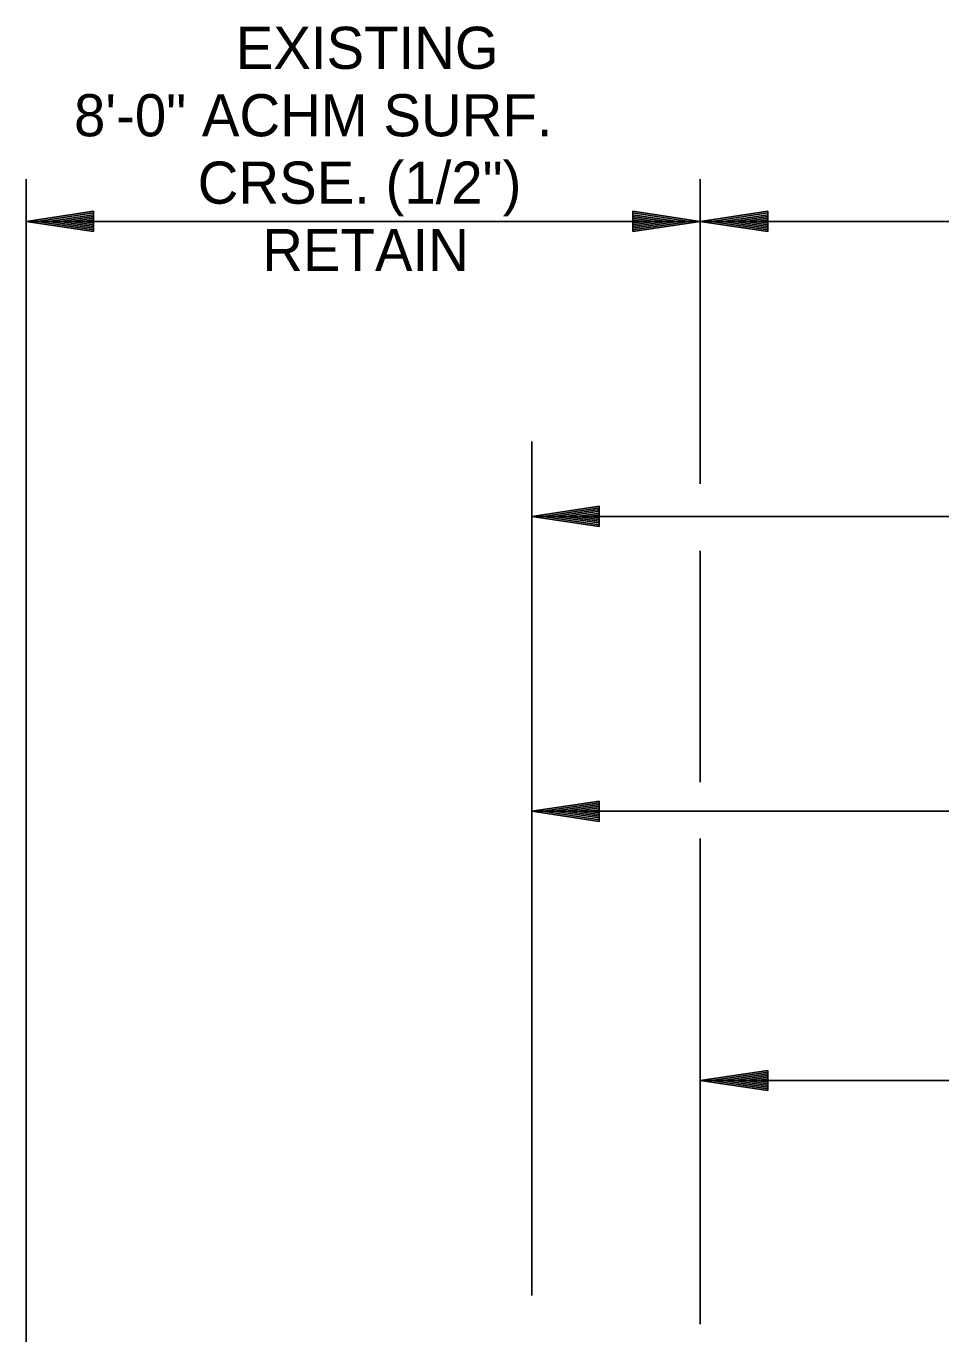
# Model space of a CAD drawing. Extents: x 60325 to 61047, y 53669 to 53767.
# Drawn here: x 60526.55 to 60537.4, y 53740.39 to 53755.91 of the extents above; entities that cross this region are included whole.
import ezdxf

# ---------------------------------------------------------------- set-up
doc = ezdxf.new("R2010")
doc.units = 0
doc.layers.add('R_Border', color=7, linetype='Continuous')
doc.layers.add('R_Border Prem', color=7, linetype='Continuous')

msp = doc.modelspace()

# ---------------------------------------------------------------- linework, layer by layer
at = {"layer": 'R_Border'}
for p, q in [((60534.545, 53740.505), (60534.545, 53744.102)), ((60535.345, 53743.516), (60534.545, 53743.396)), ((60535.345, 53743.496), (60534.679, 53743.396)), ((60535.345, 53743.516), (60535.345, 53743.276)), ((60535.345, 53743.276), (60534.545, 53743.396)), ((60534.545, 53743.396), (60562.545, 53743.396)), ((60535.345, 53743.296), (60534.679, 53743.396)), ((60535.345, 53743.476), (60534.816, 53743.396)), ((60535.345, 53743.317), (60534.816, 53743.396)), ((60535.345, 53743.456), (60534.95, 53743.396)), ((60535.345, 53743.337), (60534.95, 53743.396)), ((60535.345, 53743.435), (60535.085, 53743.396)), ((60535.345, 53743.357), (60535.085, 53743.396)), ((60535.345, 53743.415), (60535.219, 53743.396)), ((60535.345, 53743.377), (60535.219, 53743.396))]:
    msp.add_line(p, q, dxfattribs=at)
at = {"layer": 'R_Border Prem'}
for p, q in [((60526.545, 53735.251), (60526.545, 53754.091)), ((60534.545, 53750.475), (60534.545, 53754.091)), ((60527.345, 53753.711), (60526.545, 53753.591)), ((60534.545, 53753.591), (60526.545, 53753.591)), ((60527.345, 53753.471), (60526.545, 53753.591)), ((60527.345, 53753.691), (60526.679, 53753.591)), ((60527.345, 53753.491), (60526.679, 53753.591)), ((60527.345, 53753.671), (60526.816, 53753.591)), ((60527.345, 53753.512), (60526.816, 53753.591)), ((60527.345, 53753.651), (60526.95, 53753.591)), ((60527.345, 53753.532), (60526.95, 53753.591)), ((60527.345, 53753.63), (60527.085, 53753.591)), ((60527.345, 53753.552), (60527.085, 53753.591)), ((60527.345, 53753.61), (60527.219, 53753.591)), ((60527.345, 53753.572), (60527.219, 53753.591)), ((60527.345, 53753.471), (60527.345, 53753.711)), ((60533.745, 53753.711), (60534.545, 53753.591)), ((60533.745, 53753.711), (60533.745, 53753.471)), ((60533.745, 53753.691), (60534.412, 53753.591)), ((60533.745, 53753.671), (60534.274, 53753.591)), ((60533.745, 53753.651), (60534.141, 53753.591)), ((60533.745, 53753.63), (60534.005, 53753.591)), ((60533.745, 53753.61), (60533.872, 53753.591)), ((60533.745, 53753.471), (60534.545, 53753.591)), ((60533.745, 53753.552), (60534.005, 53753.591)), ((60533.745, 53753.512), (60534.274, 53753.591)), ((60533.745, 53753.491), (60534.412, 53753.591)), ((60533.745, 53753.532), (60534.141, 53753.591)), ((60533.745, 53753.572), (60533.872, 53753.591)), ((60535.345, 53753.711), (60534.545, 53753.591)), ((60608.545, 53753.591), (60534.545, 53753.591)), ((60535.345, 53753.471), (60534.545, 53753.591)), ((60535.345, 53753.691), (60534.679, 53753.591)), ((60535.345, 53753.491), (60534.679, 53753.591)), ((60535.345, 53753.671), (60534.816, 53753.591)), ((60535.345, 53753.512), (60534.816, 53753.591)), ((60535.345, 53753.651), (60534.95, 53753.591)), ((60535.345, 53753.532), (60534.95, 53753.591)), ((60535.345, 53753.63), (60535.085, 53753.591)), ((60535.345, 53753.552), (60535.085, 53753.591)), ((60535.345, 53753.61), (60535.219, 53753.591)), ((60535.345, 53753.572), (60535.219, 53753.591)), ((60535.345, 53753.471), (60535.345, 53753.711)), ((60532.545, 53740.845), (60532.545, 53750.98)), ((60533.345, 53750.211), (60532.545, 53750.091)), ((60533.345, 53750.191), (60532.679, 53750.091)), ((60533.345, 53750.171), (60532.816, 53750.091)), ((60533.345, 53749.971), (60533.345, 53750.211)), ((60610.545, 53750.091), (60532.545, 53750.091)), ((60533.345, 53749.971), (60532.545, 53750.091)), ((60533.345, 53749.991), (60532.679, 53750.091)), ((60533.345, 53750.012), (60532.816, 53750.091)), ((60533.345, 53750.151), (60532.95, 53750.091)), ((60533.345, 53750.032), (60532.95, 53750.091)), ((60533.345, 53750.13), (60533.085, 53750.091)), ((60533.345, 53750.052), (60533.085, 53750.091)), ((60533.345, 53750.11), (60533.219, 53750.091)), ((60533.345, 53750.072), (60533.219, 53750.091)), ((60534.545, 53746.936), (60534.545, 53749.68)), ((60533.345, 53746.711), (60532.545, 53746.591)), ((60533.345, 53746.691), (60532.679, 53746.591)), ((60533.345, 53746.671), (60532.816, 53746.591)), ((60533.345, 53746.651), (60532.95, 53746.591)), ((60533.345, 53746.63), (60533.085, 53746.591)), ((60533.345, 53746.61), (60533.219, 53746.591)), ((60533.345, 53746.471), (60533.345, 53746.711)), ((60610.545, 53746.591), (60532.545, 53746.591)), ((60533.345, 53746.471), (60532.545, 53746.591)), ((60533.345, 53746.491), (60532.679, 53746.591)), ((60533.345, 53746.512), (60532.816, 53746.591)), ((60533.345, 53746.532), (60532.95, 53746.591)), ((60533.345, 53746.552), (60533.085, 53746.591)), ((60533.345, 53746.572), (60533.219, 53746.591)), ((60534.545, 53740.841), (60534.545, 53746.269))]:
    msp.add_line(p, q, dxfattribs=at)

# ---------------------------------------------------------------- texts
for s, p in [('EXISTING', (60529.032, 53755.401)), ('8\'-0" ACHM SURF.', (60527.113, 53754.601)), ('CRSE. (1/2")', (60528.581, 53753.801)), ('RETAIN', (60529.347, 53753.001))]:
    msp.add_text(s, height=0.5, dxfattribs=at).set_placement(p)

doc.saveas('drawing.dxf')
